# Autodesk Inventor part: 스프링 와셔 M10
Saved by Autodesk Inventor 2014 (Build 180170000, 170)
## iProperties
Created: 2024-08
Part Number: 스프링 와셔 M10
Material: 일반
Document SubType Name: Modeling
Designer: dg
Density: 1 g/cm^3
Appearance: 기본값
Author: dg
Author: jhkim
Description: 스프링 잠금 와셔
Creation Date: 2024-08-09
Sending System: Autodesk Inventor 2025
Preprocessor: ST-DEVELOPER v20
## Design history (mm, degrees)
node "스프링 와셔 M101"
body "Solid1"
node "기준1"
